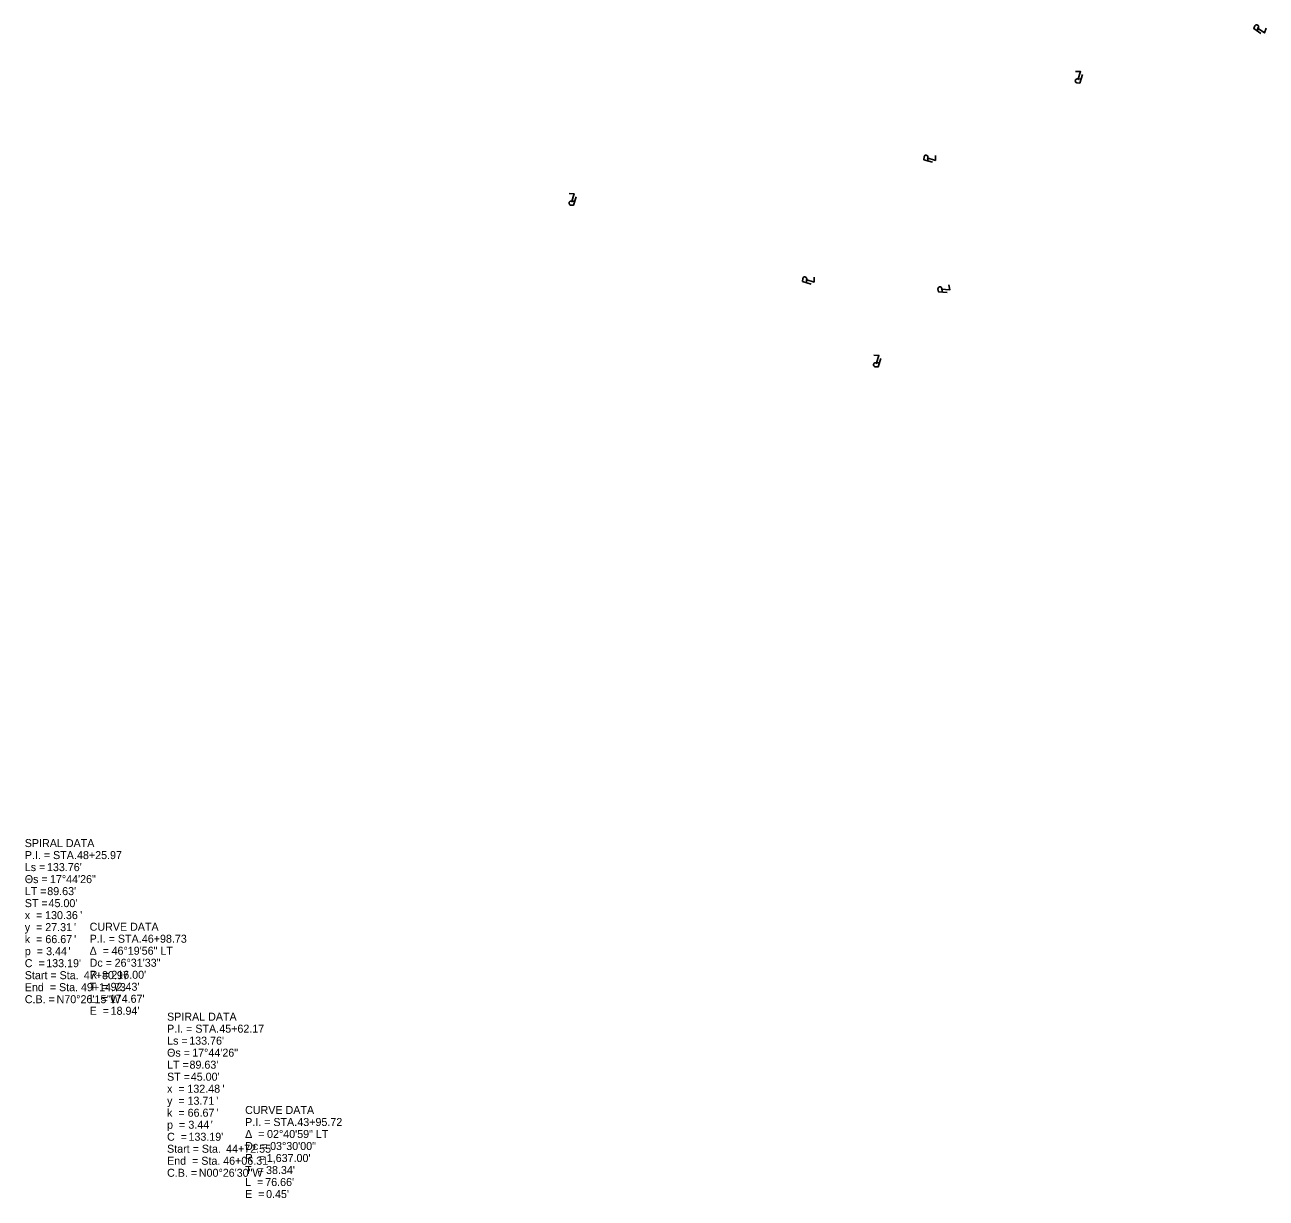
# Model space of a CAD drawing. Extents: x 2476020 to 2482399, y 282354 to 291673.
# Drawn here: x 2476695 to 2481038, y 282354 to 286458 of the extents above; entities that cross this region are included whole.
import ezdxf

# ---------------------------------------------------------------- set-up
doc = ezdxf.new("R2010")
doc.units = 0
doc.layers.add('MD_P_Surface_Chemically_Stabilized_Subgrade_Surface_Area', color=7, linetype='Continuous')
doc.layers.add('RW_P_Esmt_SL', color=7, linetype='Continuous')

msp = doc.modelspace()

# ---------------------------------------------------------------- linework, layer by layer
at = {"layer": 'RW_P_Esmt_SL'}
for p, q in [((2481006, 286436.7), (2481010.5, 286448.8)), ((2481014.6, 286442), (2481014.6, 286442)), ((2480389.9, 286268.2), (2480376.9, 286268.8)), ((2480382.1, 286274.8), (2480382.1, 286274.8)), ((2479854.2, 285982), (2479854.6, 285994.9)), ((2479860.7, 285989.8), (2479860.7, 285989.8)), ((2478618.9, 285841.2), (2478605.9, 285841.5)), ((2478611, 285847.6), (2478611, 285847.6)), ((2479429.7, 285556.6), (2479430.3, 285569.5)), ((2479436.3, 285564.3), (2479436.3, 285564.3)), ((2479905.6, 285523.3), (2479903, 285536)), ((2479910.1, 285532.4), (2479910.1, 285532.4)), ((2479684.1, 285275.3), (2479671.2, 285276)), ((2479676.4, 285282), (2479676.4, 285282))]:
    msp.add_line(p, q, dxfattribs=at)
for points in [[(2481019.4, 286427.2), (2480994.4, 286444.9), (2480998, 286454.6)], [(2481006.6, 286447.9), (2481031.5, 286430.1), (2481037.6, 286446.4)], [(2480379, 286265.3), (2480388.3, 286294.5), (2480370.8, 286295.3)], [(2480394.8, 286283.9), (2480385.6, 286254.6), (2480375.3, 286255.1)], [(2479870, 285977.3), (2479840.6, 285986), (2479840.9, 285996.3)], [(2479851.2, 285992.8), (2479880.5, 285984), (2479881, 286001.5)], [(2478608.1, 285838.1), (2478616.8, 285867.5), (2478599.3, 285867.9)], [(2478623.5, 285857), (2478614.9, 285827.6), (2478604.6, 285827.8)], [(2479445.4, 285551.6), (2479416.1, 285560.8), (2479416.6, 285571.1)], [(2479426.8, 285567.4), (2479456, 285558.1), (2479456.8, 285575.6)], [(2479922, 285522.3), (2479891.4, 285524.1), (2479889.4, 285534.2)], [(2479900.2, 285533.1), (2479930.7, 285531.2), (2479927.3, 285548.3)], [(2479673.3, 285272.5), (2479682.7, 285301.6), (2479665.2, 285302.5)], [(2479689.1, 285291), (2479679.9, 285261.8), (2479669.5, 285262.3)]]:
    msp.add_lwpolyline(points, dxfattribs=at)
for centre, start, end in [((2481004.1, 286451.2), 339.8869, 150.744), ((2480376.7, 286261.9), 87.876, 258.7331), ((2479847.7, 285995.1), 358.8569, 169.714), ((2478605.8, 285834.6), 89.0632, 259.9204), ((2479423.4, 285569.8), 357.7922, 168.6493), ((2479896.3, 285534.6), 11.9061, 182.7632), ((2479670.9, 285269.1), 87.6677, 258.5248)]:
    msp.add_arc(centre, 6.9, start, end, dxfattribs=at)

# ---------------------------------------------------------------- texts
at = {"layer": 'MD_P_Surface_Chemically_Stabilized_Subgrade_Surface_Area'}
for s, p in [('SPIRAL DATA', (2476695.1, 283582.1)), ('P.I. = STA. ', (2476695.1, 283540.1)), ('48+25.97', (2476877.8, 283540.1)), ('Ls = ', (2476695.1, 283498.1)), ("133.76'", (2476772.7, 283498.1)), ('Θs = ', (2476695.1, 283456.1)), ('17°44\'26"', (2476783.2, 283456.1)), ('LT = ', (2476695.1, 283414.1)), ("89.63'", (2476773.7, 283414.1)), ('ST = ', (2476695.1, 283372.1)), ("45.00'", (2476778.2, 283372.1)), ('x  = ', (2476695.1, 283330.1)), ('130.36', (2476766.1, 283330.1)), ("'", (2476889, 283330.1)), ('y  = ', (2476695.1, 283288.1)), ('27.31', (2476766.7, 283288.1)), ("'", (2476867.3, 283288.1)), ('CURVE DATA', (2476921.9, 283289.6)), ('k  = ', (2476695.1, 283246.1)), ('66.67', (2476767.1, 283246.1)), ("'", (2476867.6, 283246.1)), ('P.I. = STA. ', (2476921.9, 283247.6)), ('46+98.73', (2477104.6, 283247.6)), ('p  = ', (2476695.1, 283204.1)), ('3.44', (2476769.7, 283204.1)), ("'", (2476847.9, 283204.1)), ('Δ  = ', (2476921.9, 283205.6)), ('46°19\'56" LT', (2476998.7, 283205.6)), ('C  = ', (2476695.1, 283162.1)), ("133.19'", (2476770.1, 283162.1)), ('Dc = ', (2476921.9, 283163.6)), ('26°31\'33"', (2477009.3, 283163.6)), ('Start = Sta. ', (2476695.1, 283120.1)), ('47+80.97', (2476901.7, 283120.1)), ('R  = ', (2476921.9, 283121.6)), ("216.00'", (2476997.8, 283121.6)), ('End  = Sta. ', (2476695.1, 283078.1)), ('49+14.73', (2476891.5, 283078.1)), ('T  = ', (2476921.9, 283079.6)), ("92.43'", (2476995.3, 283079.6)), ('C.B. = ', (2476695.1, 283036.1)), ('N70°26\'15"W', (2476806.4, 283036.1)), ('L  = ', (2476921.9, 283037.6)), ("174.67'", (2476992.3, 283037.6)), ('E  = ', (2476921.9, 282995.6)), ("18.94'", (2476995.3, 282995.6)), ('SPIRAL DATA', (2477192.8, 282975)), ('P.I. = STA. ', (2477192.8, 282933)), ('45+62.17', (2477375.4, 282933)), ('Ls = ', (2477192.8, 282891)), ("133.76'", (2477270.4, 282891)), ('Θs = ', (2477192.8, 282849)), ('17°44\'26"', (2477280.8, 282849)), ('LT = ', (2477192.8, 282807)), ("89.63'", (2477271.3, 282807)), ('ST = ', (2477192.8, 282765)), ("45.00'", (2477275.8, 282765)), ('x  = ', (2477192.8, 282723)), ('132.48', (2477263.8, 282723)), ("'", (2477386.6, 282723)), ('y  = ', (2477192.8, 282681)), ('13.71', (2477264.4, 282681)), ("'", (2477364.9, 282681)), ('k  = ', (2477192.8, 282639)), ('66.67', (2477264.7, 282639)), ("'", (2477365.2, 282639)), ('CURVE DATA', (2477465.8, 282648.6)), ('p  = ', (2477192.8, 282597)), ('3.44', (2477267.3, 282597)), ("'", (2477345.5, 282597)), ('P.I. = STA. ', (2477465.8, 282606.6)), ('43+95.72', (2477648.4, 282606.6)), ('C  = ', (2477192.8, 282555)), ("133.19'", (2477267.7, 282555)), ('Δ  = ', (2477465.8, 282564.6)), ('02°40\'59" LT', (2477542.5, 282564.6)), ('Start = Sta. ', (2477192.8, 282513)), ('44+72.55', (2477399.3, 282513)), ('Dc = ', (2477465.8, 282522.6)), ('03°30\'00"', (2477553.2, 282522.6)), ('End  = Sta. ', (2477192.8, 282471)), ('46+06.31', (2477389.1, 282471)), ('R  = ', (2477465.8, 282480.6)), ("1,637.00'", (2477541.6, 282480.6)), ('C.B. = ', (2477192.8, 282429)), ('N00°26\'30"W', (2477304, 282429)), ('T  = ', (2477465.8, 282438.6)), ("38.34'", (2477539.1, 282438.6)), ('L  = ', (2477465.8, 282396.6)), ("76.66'", (2477536.2, 282396.6)), ('E  = ', (2477465.8, 282354.6)), ("0.45'", (2477539.2, 282354.6))]:
    msp.add_text(s, height=28, dxfattribs=at).set_placement(p)

doc.saveas('drawing.dxf')
